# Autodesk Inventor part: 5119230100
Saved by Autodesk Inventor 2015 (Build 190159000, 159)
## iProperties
Created: 2020-07
Part Number: 5119230100
Checked By: TraceParts S.A.
Material: Generic
Catalog Web Link: www.traceparts.com
Document SubType Name: Modeling
Designer: TraceParts
Density: 1 g/cm^3
Appearance: Default
Company: TraceParts S.A.
Author: TraceParts
REFERENCE: 5119230100
DESIGN: HIB-1250 P 0,75KW (230V 50HZ) - 5119230100
SUPPLIER: Soler & Palau
TraceParts.PartNumber: 10-20122018-119595
TraceParts.PartTitle: HIB-P/HIT-P
TraceParts.InstanceId: 10-20122018-119595EL9VDQVQ4B55ZKJ0885QNCS1H
TraceParts.PartStatus: Published
TraceParts.PartVersion: 1.0.2
TRACEPARTS: TRACEPARTS
TraceParts.PartLanguage: en
TraceParts.ClassPath: SOLER_PALAU:10-20122018-119595
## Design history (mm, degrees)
feature "5119230100"
body "Solid1"
